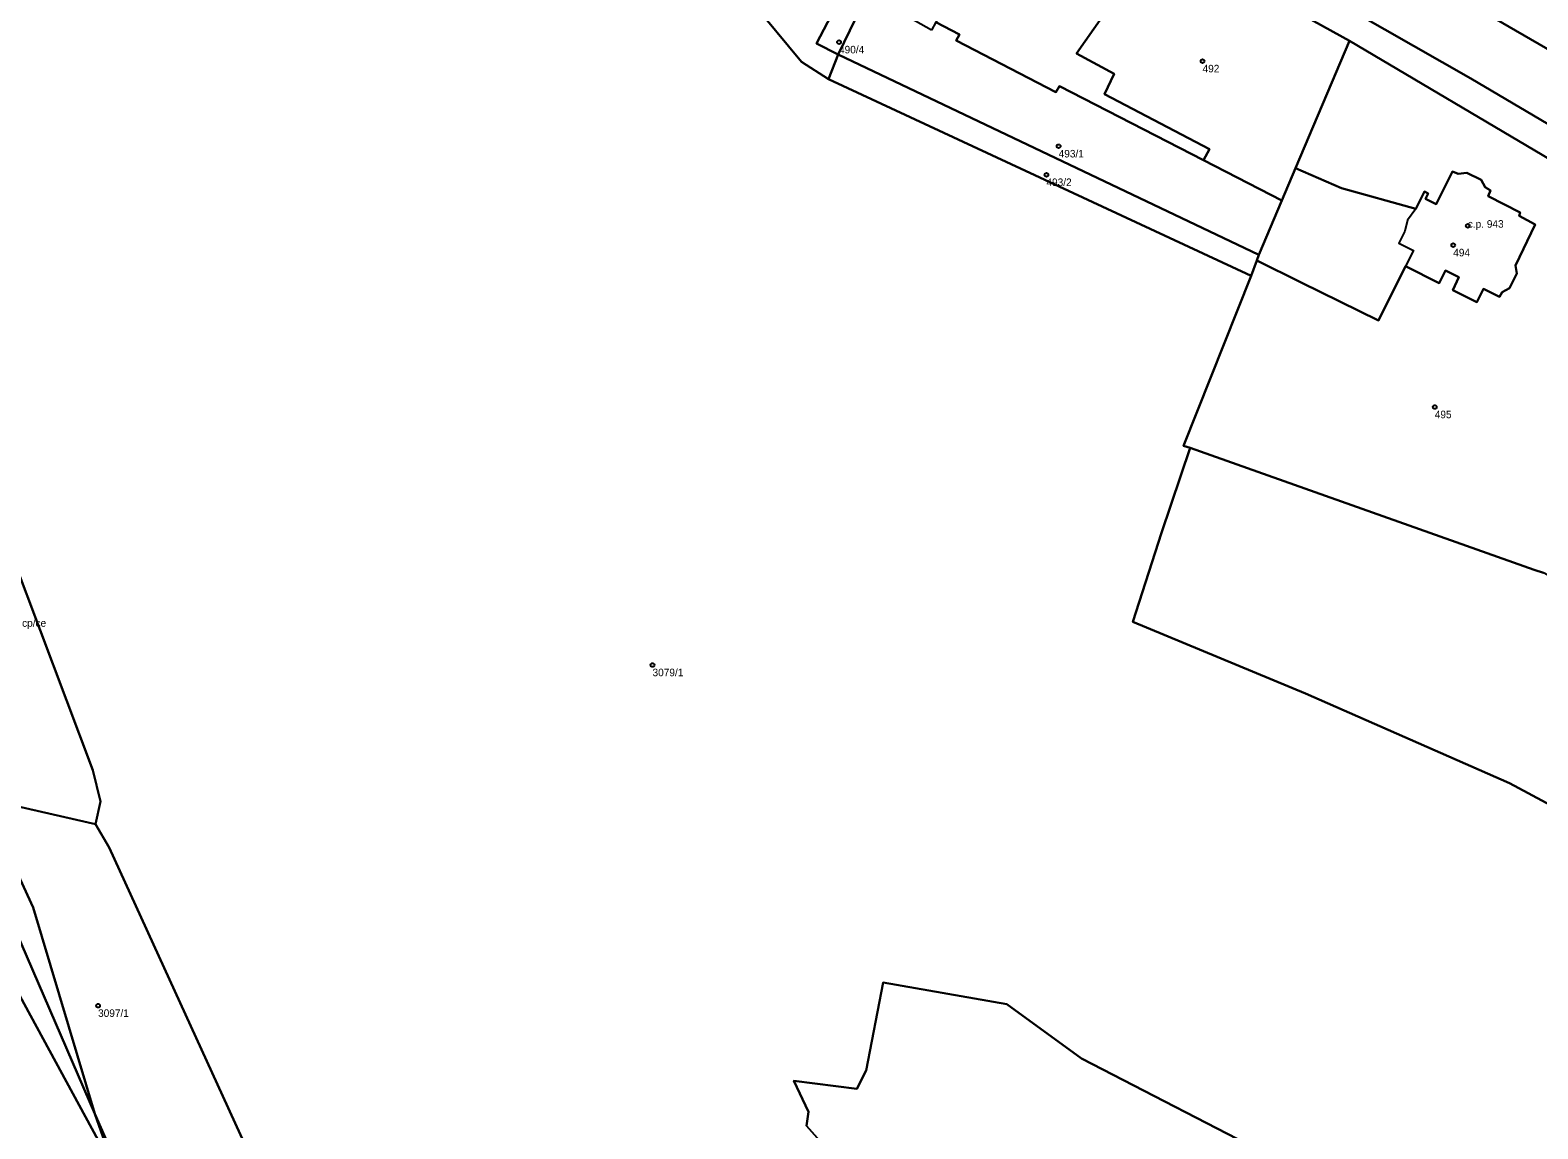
# Model space of a CAD drawing. Extents: x -878211 to -870363, y -1058464 to -1052522.
# Drawn here: x -874067.3 to -873867.2, y -1056571.4 to -1056425.6 of the extents above; entities that cross this region are included whole.
import ezdxf

# ---------------------------------------------------------------- set-up
doc = ezdxf.new("R2010")
doc.units = 0
for name, color, linetype in [('Vrstva 50', 7, 'Continuous'), ('Vrstva 51', 7, 'Continuous'), ('Vrstva 52', 7, 'Continuous')]:
    doc.layers.add(name, color=color, linetype=linetype)

msp = doc.modelspace()

# ---------------------------------------------------------------- linework, layer by layer
at = {"layer": 'Vrstva 50'}
for centre in [(-873959.99, -1056427.17994), (-873911.74, -1056429.69994), (-873930.84, -1056440.98994), (-873932.46, -1056444.77994), (-873876.54, -1056451.54994), (-873878.47, -1056454.10994), (-873880.92, -1056475.58994), (-873984.74, -1056509.81994), (-874058.33, -1056555.01994)]:
    msp.add_circle(centre, 0.25, dxfattribs=at)
at = {"layer": 'Vrstva 51'}
for points in [[(-874003.62, -1056314.46), (-874016.65, -1056316.8), (-874016.52, -1056323.42), (-874020.22, -1056334.71), (-874008.04, -1056345.96), (-873856.57, -1056433.51)], [(-873856.57, -1056433.51), (-874008.04, -1056345.96)], [(-873847.51, -1056448.88), (-873876.13, -1056432), (-873926.22, -1056403.42), (-873955.28, -1056386.42), (-873953.76, -1056387.4), (-873943.35, -1056394.14), (-873943.79, -1056395.05), (-873944.81, -1056397.15), (-873936.47, -1056401.3), (-873932.43, -1056403.66), (-873927.7, -1056406.62), (-873917.49, -1056413.02), (-873892.23, -1056426.99), (-873838.7, -1056458.67)], [(-873898.09, -1056513.59), (-873921, -1056504.08), (-873917.2, -1056492.27), (-873913.39, -1056481), (-873914.25, -1056480.76), (-873905.3, -1056458.17), (-873961.38, -1056432.1), (-873964.96, -1056429.77), (-873978.35, -1056413.65), (-873998.01, -1056389.1)], [(-873895.24, -1056850.14), (-873908.21, -1056824.62), (-873940.24, -1056755.07), (-873950.29, -1056741.89), (-873967.11, -1056720.96), (-873969.65, -1056722.8), (-873973.32, -1056718.02), (-874002.89, -1056678.66), (-874011.69, -1056666.89), (-874009.12, -1056664.87), (-874011.97, -1056661.51), (-874024.62, -1056638.91), (-874042.06, -1056605.74), (-874043.43, -1056601.67), (-874041.78, -1056601.01), (-874055.1, -1056577.75), (-874058.74, -1056569.35), (-874056.05, -1056577), (-874084.77, -1056524.21), (-874108.38, -1056481.4), (-874117.36, -1056461.73), (-874136.62, -1056429.22), (-874154.14, -1056399.02)], [(-873926.22, -1056403.42), (-873876.13, -1056432), (-873847.51, -1056448.88)], [(-874089.4, -1056424.57), (-874093.72, -1056425.61), (-874091.26, -1056427.37), (-874086.97, -1056446.13), (-874080.24, -1056469.1), (-874069.52, -1056495.93), (-874059.02, -1056523.78), (-874058.03, -1056527.95), (-874058.67, -1056530.92), (-874056.84, -1056534.05), (-874035.88, -1056579.88), (-874041.25, -1056593.06), (-874019.42, -1056638.08), (-874011.45, -1056652.11), (-873975.84, -1056699.09), (-873943.35, -1056736.97), (-873935.01, -1056752.39), (-873930.75, -1056761.9), (-873920.07, -1056788.11), (-873906.75, -1056817.03), (-873873.73, -1056840.56), (-873864.45, -1056848.53)], [(-873838.7, -1056458.67), (-873892.23, -1056426.99), (-873899.4, -1056443.9), (-873898.4, -1056444.33), (-873893.29, -1056446.54), (-873883.44, -1056449.31), (-873882.29, -1056447.01), (-873881.8, -1056447.25), (-873882.15, -1056447.95), (-873880.75, -1056448.68), (-873878.55, -1056444.35), (-873877.81, -1056444.67), (-873876.68, -1056444.52), (-873874.77, -1056445.46), (-873874.23, -1056446.44), (-873873.52, -1056446.85), (-873873.83, -1056447.6), (-873869.59, -1056449.76), (-873869.73, -1056450.24), (-873867.59, -1056451.37), (-873870.2, -1056456.8), (-873870.04, -1056457.88), (-873870.99, -1056459.8), (-873871.98, -1056460.33), (-873872.31, -1056460.99), (-873874.47, -1056459.91), (-873875.35, -1056461.67), (-873878.51, -1056460.07), (-873877.72, -1056458.35), (-873879.5, -1056457.49), (-873880.33, -1056459.14), (-873884.81, -1056456.92), (-873888.39, -1056464.12), (-873898.64, -1056459.05), (-873904.55, -1056456.13), (-873905.3, -1056458.17), (-873914.25, -1056480.76), (-873913.39, -1056481), (-873867.73, -1056497.18), (-873866.47, -1056497.57)], [(-873824.39, -1056550.48), (-873871.02, -1056525.51), (-873898.09, -1056513.59)], [(-873848.21, -1056602.58), (-873877.08, -1056587.35), (-873888.38, -1056581.55), (-873901.59, -1056575.57), (-873927.8, -1056562.03), (-873937.73, -1056554.81), (-873954.15, -1056551.94), (-873956.39, -1056563.62), (-873957.61, -1056566.06), (-873965.97, -1056564.98), (-873964.04, -1056569.09), (-873964.29, -1056570.98), (-873960.73, -1056574.98), (-873959.1, -1056591.29), (-873924.36, -1056601.58), (-873868.18, -1056627.06), (-873841.71, -1056644.24)], [(-873841.71, -1056644.24), (-873868.18, -1056627.06), (-873924.36, -1056601.58), (-873959.1, -1056591.29), (-873960.73, -1056574.98), (-873964.29, -1056570.98), (-873964.04, -1056569.09), (-873965.97, -1056564.98), (-873957.61, -1056566.06), (-873956.39, -1056563.62), (-873954.15, -1056551.94), (-873937.73, -1056554.81), (-873927.8, -1056562.03), (-873901.59, -1056575.57), (-873888.38, -1056581.55), (-873877.08, -1056587.35), (-873848.21, -1056602.58)]]:
    msp.add_lwpolyline(points, dxfattribs=at)
for points in [[(-873955.29, -1056412.65), (-873964.58, -1056407.88), (-873968.71, -1056397.89), (-873983.71, -1056392.31), (-873972.24, -1056400.13), (-873970.89, -1056405.44), (-873978.35, -1056413.65), (-873964.96, -1056429.77), (-873961.38, -1056432.1), (-873960.11, -1056428.84), (-873962.99, -1056427.37)], [(-873932.43, -1056403.66), (-873936.47, -1056401.3), (-873944.81, -1056397.15), (-873952.9, -1056413.88), (-873953.43, -1056414.97), (-873944.56, -1056419.98), (-873947.12, -1056424.52), (-873944.01, -1056426.16), (-873944.45, -1056426.98), (-873931.21, -1056433.8), (-873930.74, -1056433.01), (-873911.61, -1056442.82), (-873910.82, -1056441.38), (-873924.77, -1056434.07), (-873923.48, -1056431.37), (-873928.47, -1056428.69), (-873917.49, -1056413.02), (-873927.7, -1056406.62)], [(-873953.43, -1056414.97), (-873952.9, -1056413.88), (-873955.29, -1056412.65), (-873962.99, -1056427.37), (-873960.11, -1056428.84), (-873956.22, -1056420.76), (-873958.49, -1056419.48), (-873955.06, -1056414.05)], [(-873917.49, -1056413.02), (-873928.47, -1056428.69), (-873923.48, -1056431.37), (-873924.77, -1056434.07), (-873910.82, -1056441.38), (-873911.61, -1056442.82), (-873901.21, -1056448.18), (-873899.4, -1056443.9), (-873892.23, -1056426.99)], [(-873947.71, -1056425.57), (-873956.22, -1056420.76), (-873960.11, -1056428.84), (-873904.28, -1056455.41), (-873901.21, -1056448.18), (-873911.61, -1056442.82), (-873930.74, -1056433.01), (-873931.21, -1056433.8), (-873944.45, -1056426.98), (-873944.01, -1056426.16), (-873947.12, -1056424.52)], [(-873905.3, -1056458.17), (-873904.55, -1056456.13), (-873904.28, -1056455.41), (-873960.11, -1056428.84), (-873961.38, -1056432.1)], [(-873879.5, -1056457.49), (-873877.72, -1056458.35), (-873878.51, -1056460.07), (-873875.35, -1056461.67), (-873874.47, -1056459.91), (-873872.31, -1056460.99), (-873871.98, -1056460.33), (-873870.99, -1056459.8), (-873870.04, -1056457.88), (-873870.2, -1056456.8), (-873867.59, -1056451.37), (-873869.73, -1056450.24), (-873869.59, -1056449.76), (-873873.83, -1056447.6), (-873873.52, -1056446.85), (-873874.23, -1056446.44), (-873874.77, -1056445.46), (-873876.68, -1056444.52), (-873877.81, -1056444.67), (-873878.55, -1056444.35), (-873880.75, -1056448.68), (-873882.15, -1056447.95), (-873881.8, -1056447.25), (-873882.29, -1056447.01), (-873883.44, -1056449.31), (-873893.29, -1056446.54), (-873898.4, -1056444.33), (-873899.4, -1056443.9), (-873901.21, -1056448.18), (-873904.28, -1056455.41), (-873904.55, -1056456.13), (-873898.64, -1056459.05), (-873888.39, -1056464.12), (-873884.81, -1056456.92), (-873880.33, -1056459.14)], [(-874097.18, -1056496.94), (-874106.82, -1056479.54), (-874117.36, -1056461.73), (-874108.38, -1056481.4), (-874084.77, -1056524.21), (-874056.05, -1056577), (-874058.74, -1056569.35), (-874070.76, -1056541.63), (-874078.23, -1056526.48)], [(-873866.47, -1056497.57), (-873867.73, -1056497.18), (-873913.39, -1056481), (-873917.2, -1056492.27), (-873921, -1056504.08), (-873898.09, -1056513.59), (-873871.02, -1056525.51), (-873824.39, -1056550.48), (-873810.92, -1056557.78), (-873798.01, -1056567.46), (-873778.72, -1056549.39), (-873787.4, -1056542.91), (-873796.15, -1056535.38), (-873826.79, -1056518.94), (-873844.78, -1056509.27)], [(-874069.52, -1056495.93), (-874072.34, -1056497.46), (-874077.27, -1056499.42), (-874078.64, -1056495.93), (-874080.77, -1056490.34), (-874082.65, -1056491.07), (-874083.83, -1056488.11), (-874097.18, -1056496.94), (-874078.23, -1056526.48), (-874073.61, -1056527.53), (-874058.67, -1056530.92), (-874058.03, -1056527.95), (-874059.02, -1056523.78)], [(-874078.23, -1056526.48), (-874070.76, -1056541.63), (-874058.74, -1056569.35), (-874066.94, -1056541.99), (-874073.61, -1056527.53)], [(-874058.74, -1056569.35), (-874055.1, -1056577.75), (-874041.78, -1056601.01), (-874035.4, -1056613.17), (-874011.89, -1056655.9), (-873946.72, -1056739.16), (-873936.35, -1056752.76), (-873920.07, -1056788.11), (-873930.75, -1056761.9), (-873935.01, -1056752.39), (-873943.35, -1056736.97), (-873975.84, -1056699.09), (-874011.45, -1056652.11), (-874019.42, -1056638.08), (-874041.25, -1056593.06), (-874035.88, -1056579.88), (-874056.84, -1056534.05), (-874058.67, -1056530.92), (-874073.61, -1056527.53), (-874066.94, -1056541.99)]]:
    msp.add_lwpolyline(points, close=True, dxfattribs=at)
at = {"layer": 'Vrstva 52'}
msp.add_lwpolyline([(-873877.72, -1056458.35), (-873878.51, -1056460.07), (-873875.35, -1056461.67), (-873874.47, -1056459.91), (-873872.31, -1056460.99), (-873871.98, -1056460.33), (-873870.99, -1056459.8), (-873870.04, -1056457.88), (-873870.2, -1056456.8), (-873867.59, -1056451.37), (-873869.73, -1056450.24), (-873869.59, -1056449.76), (-873873.83, -1056447.6), (-873873.52, -1056446.85), (-873874.23, -1056446.44), (-873874.77, -1056445.46), (-873876.68, -1056444.52), (-873877.81, -1056444.67), (-873878.55, -1056444.35), (-873880.75, -1056448.68), (-873882.15, -1056447.95), (-873881.8, -1056447.25), (-873882.29, -1056447.01), (-873883.44, -1056449.31), (-873884.55, -1056450.8), (-873884.91, -1056452.25), (-873885.69, -1056453.86), (-873883.76, -1056454.84), (-873884.81, -1056456.92), (-873880.33, -1056459.14), (-873879.5, -1056457.49)], close=True, dxfattribs=at)

# ---------------------------------------------------------------- texts
at = {"layer": 'Vrstva 50'}
for s, p in [('490/4', (-873959.99, -1056428.669)), ('492', (-873911.74, -1056431.189)), ('493/1', (-873930.84, -1056442.479)), ('493/2', (-873932.46, -1056446.269)), ('c.p. 943', (-873876.54, -1056451.8)), ('494', (-873878.47, -1056455.599)), ('495', (-873880.92, -1056477.079)), ('bez cp/ce', (-874070.94, -1056504.75)), ('3079/1', (-873984.74, -1056511.309)), ('3097/1', (-874058.33, -1056556.509))]:
    msp.add_text(s, height=0.999996, dxfattribs=at).set_placement(p)

doc.saveas('drawing.dxf')
